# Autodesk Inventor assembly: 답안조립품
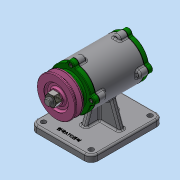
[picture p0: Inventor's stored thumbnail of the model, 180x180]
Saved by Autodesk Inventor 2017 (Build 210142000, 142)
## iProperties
Part Number: 답안조립품
Material: 일반
Document SubType Name: Assembly
Designer: MRC
Author: MRC
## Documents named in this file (12)
- C:\Users\MRC\Desktop\720716V1004\답안조립품.iam
- C:\Users\MRC\Desktop\720716V1004\본체.ipt
- C:\Users\MRC\Desktop\720716V1004\볼트 M4 x 12.ipt
- C:\Users\MRC\Desktop\720716V1004\앞커버.ipt
- C:\Users\MRC\Desktop\720716V1004\오일 실.ipt
- C:\Users\MRC\Desktop\720716V1004\축.ipt
- C:\Users\MRC\Desktop\720716V1004\키 4 x 4.ipt
- C:\Users\MRC\Desktop\720716V1004\뒤커버.ipt
- C:\Users\MRC\Desktop\720716V1004\베어링 6204.ipt
- C:\Users\MRC\Desktop\720716V1004\개스킷.ipt
- C:\Users\MRC\Desktop\720716V1004\너트 M12 x 1.25.ipt
- C:\Users\MRC\Desktop\720716V1004\V-벨트풀리.ipt
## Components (3 placed, 2 different names)
1. 개스킷:1
2. 개스킷:2
3. V-벨트풀리:1
